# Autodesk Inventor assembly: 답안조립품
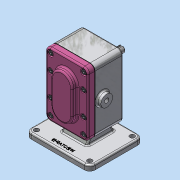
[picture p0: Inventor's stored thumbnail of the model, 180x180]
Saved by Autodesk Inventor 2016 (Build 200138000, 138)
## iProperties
Created: 2020-04
Part Number: 답안조립품
Material: 일반
Document SubType Name: Assembly
Designer: Administrator
Author: Administrator
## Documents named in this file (11)
- C:\Users\Administrator\Desktop\700407V1034\답안조립품.iam
- C:\Users\Administrator\Desktop\700407V1034\본체.ipt
- C:\Users\Administrator\Desktop\700407V1034\베어링부시.ipt
- C:\Users\Administrator\Desktop\700407V1034\메인축.ipt
- C:\Users\Administrator\Desktop\700407V1034\키 6 x 6 x 18.ipt
- C:\Users\Administrator\Desktop\700407V1034\서브축.ipt
- C:\Users\Administrator\Desktop\700407V1034\스퍼기어.ipt
- C:\Users\Administrator\Desktop\700407V1034\오일 실 16 28 7.ipt
- C:\Users\Administrator\Desktop\700407V1034\커버.ipt
- C:\Users\Administrator\Desktop\700407V1034\개스킷.ipt
- C:\Users\Administrator\Desktop\700407V1034\볼트 M5.ipt
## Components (1 placed, 1 different names)
1. 개스킷:1
